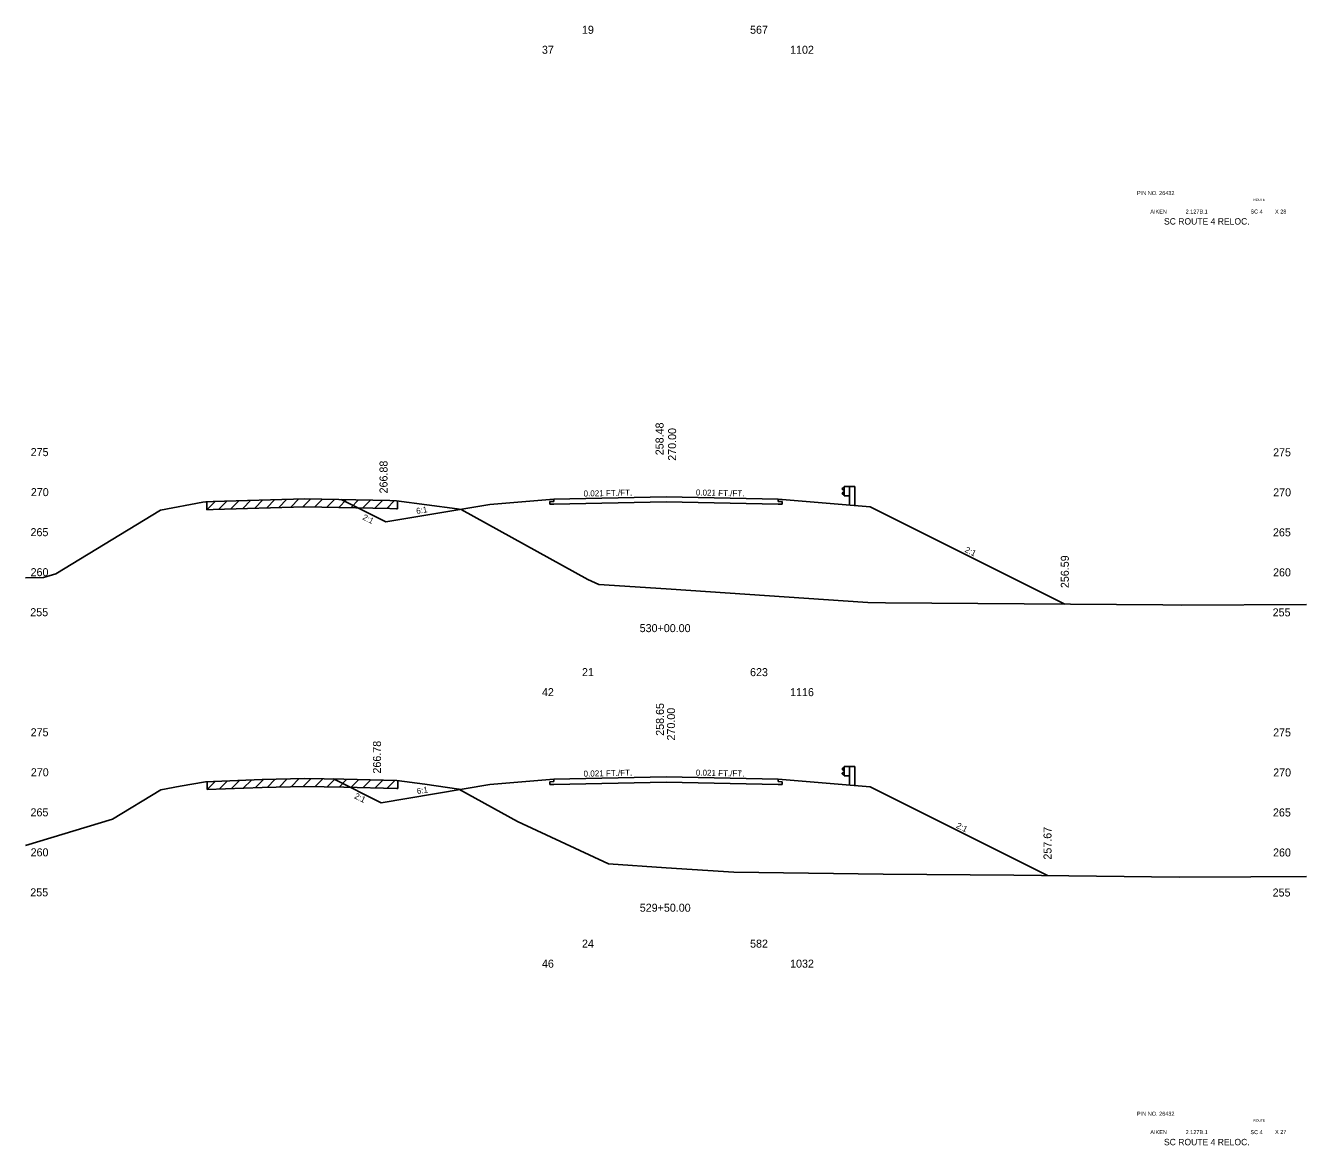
# Model space of a CAD drawing. Extents: x 2967 to 4323, y -3677 to -817.
# Drawn here: x 3555.3 to 3715.3, y -3465.9 to -3326 of the extents above; entities that cross this region are included whole.
import ezdxf

# ---------------------------------------------------------------- set-up
doc = ezdxf.new("R2010")
doc.units = 0
for name, color, linetype in [('Level 1', 7, 'Continuous'), ('Level 10', 7, 'Continuous'), ('Level 11', 7, 'Continuous'), ('Level 12', 7, 'Continuous'), ('Level 20', 7, 'Continuous'), ('Level 24', 7, 'Continuous'), ('Level 3', 7, 'Continuous'), ('Level 32', 7, 'Continuous'), ('Level 33', 7, 'Continuous'), ('Level 59', 7, 'Continuous'), ('Level 6', 7, 'Continuous'), ('Level 60', 7, 'Continuous'), ('Level 61', 7, 'Continuous'), ('Level 7', 7, 'Continuous')]:
    doc.layers.add(name, color=color, linetype=linetype)

msp = doc.modelspace()

# ---------------------------------------------------------------- linework, layer by layer
at = {"layer": 'Level 11'}
for p, q in [((3621.35, -3385.43), (3620.85, -3385.44)), ((3620.85, -3385.44), (3620.85, -3385.78)), ((3621.35, -3385.13), (3621.35, -3385.43)), ((3649.35, -3385.43), (3649.35, -3385.13)), ((3649.85, -3385.44), (3649.35, -3385.43)), ((3649.85, -3385.78), (3649.85, -3385.44)), ((3620.85, -3385.78), (3621.35, -3385.77)), ((3649.35, -3385.77), (3649.85, -3385.78)), ((3621.35, -3420.43), (3620.85, -3420.44)), ((3620.85, -3420.44), (3620.85, -3420.78)), ((3620.85, -3420.78), (3621.35, -3420.77)), ((3621.35, -3420.13), (3621.35, -3420.43)), ((3649.35, -3420.43), (3649.35, -3420.13)), ((3649.85, -3420.44), (3649.35, -3420.43)), ((3649.35, -3420.77), (3649.85, -3420.78)), ((3649.85, -3420.78), (3649.85, -3420.44))]:
    msp.add_line(p, q, dxfattribs=at)
at = {"layer": 'Level 12'}
for p, q in [((3635.35, -3385.48), (3621.35, -3385.77)), ((3649.35, -3385.77), (3635.35, -3385.48)), ((3635.35, -3420.48), (3621.35, -3420.77)), ((3649.35, -3420.77), (3635.35, -3420.48))]:
    msp.add_line(p, q, dxfattribs=at)
at = {"layer": 'Level 24'}
for p, q in [((3657.62, -3383.62), (3657.35, -3383.82)), ((3657.35, -3383.82), (3657.35, -3383.87)), ((3657.35, -3383.87), (3657.62, -3384.07)), ((3657.62, -3384.72), (3657.62, -3383.55)), ((3657.62, -3383.55), (3658.28, -3383.55)), ((3658.28, -3383.55), (3658.28, -3385.88)), ((3658.28, -3383.55), (3658.95, -3383.55)), ((3658.95, -3383.55), (3658.95, -3385.93)), ((3657.35, -3384.39), (3657.62, -3384.19)), ((3657.35, -3384.44), (3657.35, -3384.39)), ((3657.62, -3384.64), (3657.35, -3384.44)), ((3657.62, -3384.72), (3658.29, -3384.72)), ((3657.62, -3418.62), (3657.35, -3418.82)), ((3657.35, -3418.82), (3657.35, -3418.87)), ((3657.35, -3418.87), (3657.62, -3419.07)), ((3657.35, -3419.39), (3657.62, -3419.19)), ((3657.62, -3419.72), (3657.62, -3418.55)), ((3657.62, -3418.55), (3658.28, -3418.55)), ((3658.28, -3418.55), (3658.28, -3420.88)), ((3658.28, -3418.55), (3658.95, -3418.55)), ((3658.95, -3418.55), (3658.95, -3420.93)), ((3657.35, -3419.44), (3657.35, -3419.39)), ((3657.62, -3419.64), (3657.35, -3419.44)), ((3657.62, -3419.72), (3658.29, -3419.72))]:
    msp.add_line(p, q, dxfattribs=at)
at = {"layer": 'Level 59'}
for p, q in [((3621.35, -3385.13), (3635.35, -3384.84)), ((3635.35, -3384.84), (3649.35, -3385.13)), ((3621.35, -3420.13), (3635.35, -3419.84)), ((3635.35, -3419.84), (3649.35, -3420.13))]:
    msp.add_line(p, q, dxfattribs=at)
at = {"layer": 'Level 6'}
for p, q in [((3613.35, -3385.8), (3621.35, -3385.13)), ((3649.35, -3385.13), (3657.35, -3385.8)), ((3657.35, -3385.8), (3660.85, -3386.09)), ((3613.35, -3420.8), (3621.35, -3420.13)), ((3649.35, -3420.13), (3657.35, -3420.8)), ((3657.35, -3420.8), (3660.85, -3421.09))]:
    msp.add_line(p, q, dxfattribs=at)
at = {"layer": 'Level 60'}
for p, q in [((3572.21, -3386.52), (3577.47, -3385.53)), ((3577.47, -3385.53), (3577.87, -3385.46)), ((3577.87, -3385.46), (3578.77, -3385.43)), ((3578.77, -3385.43), (3590.24, -3385.08)), ((3590.24, -3385.08), (3600.84, -3385.31)), ((3600.84, -3385.31), (3601.66, -3385.33)), ((3601.66, -3385.33), (3609.24, -3386.33)), ((3559.12, -3394.48), (3572.21, -3386.52)), ((3609.24, -3386.33), (3609.76, -3386.41)), ((3609.76, -3386.41), (3625.6, -3395.16)), ((3555.35, -3394.95), (3557.57, -3394.94)), ((3557.57, -3394.94), (3559.12, -3394.48)), ((3625.6, -3395.16), (3626.97, -3395.8)), ((3626.97, -3395.8), (3635.35, -3396.36)), ((3635.35, -3396.36), (3660.58, -3398.04)), ((3660.58, -3398.04), (3662.76, -3398.07)), ((3662.76, -3398.07), (3697.42, -3398.35)), ((3697.42, -3398.35), (3699.76, -3398.38)), ((3699.76, -3398.38), (3715.35, -3398.31)), ((3574.66, -3420.99), (3577.82, -3420.44)), ((3577.82, -3420.44), (3584.91, -3420.18)), ((3584.91, -3420.18), (3590.2, -3420.02)), ((3590.2, -3420.02), (3595.09, -3420.12)), ((3595.09, -3420.12), (3601.72, -3420.29)), ((3601.72, -3420.29), (3605.22, -3420.75)), ((3605.22, -3420.75), (3609.48, -3421.37)), ((3566.19, -3425.12), (3572.23, -3421.45)), ((3572.23, -3421.45), (3574.66, -3420.99)), ((3609.48, -3421.37), (3616.8, -3425.42)), ((3555.35, -3428.39), (3566.19, -3425.12)), ((3616.8, -3425.42), (3628.18, -3430.71)), ((3628.18, -3430.71), (3635.35, -3431.19)), ((3635.35, -3431.19), (3643.83, -3431.75)), ((3643.83, -3431.75), (3662.47, -3431.99)), ((3662.47, -3431.99), (3678.79, -3432.13)), ((3678.79, -3432.13), (3699.47, -3432.36)), ((3699.47, -3432.36), (3708.41, -3432.32)), ((3708.41, -3432.32), (3715.35, -3432.29))]:
    msp.add_line(p, q, dxfattribs=at)
at = {"layer": 'Level 61'}
for p, q in [((3579.01, -3385.42), (3577.97, -3386.46)), ((3577.97, -3385.46), (3577.97, -3386.46)), ((3580.5, -3385.37), (3579.47, -3386.4)), ((3582, -3385.33), (3580.97, -3386.36)), ((3583.5, -3385.28), (3582.47, -3386.31)), ((3585, -3385.24), (3583.97, -3386.27)), ((3586.5, -3385.19), (3585.47, -3386.23)), ((3588, -3385.15), (3586.97, -3386.18)), ((3589.5, -3385.1), (3588.47, -3386.14)), ((3590.96, -3385.1), (3589.97, -3386.09)), ((3592.45, -3385.13), (3591.47, -3386.11)), ((3593.95, -3385.16), (3592.97, -3386.14)), ((3595.45, -3385.19), (3594.47, -3386.17)), ((3596.95, -3385.22), (3595.97, -3386.2)), ((3598.45, -3385.26), (3597.47, -3386.23)), ((3599.95, -3385.29), (3598.97, -3386.27)), ((3601.45, -3385.32), (3600.47, -3386.3)), ((3601.82, -3386.35), (3601.82, -3385.35)), ((3577.97, -3386.46), (3578.77, -3386.43)), ((3578.77, -3386.43), (3590.24, -3386.08)), ((3590.24, -3386.08), (3600.84, -3386.31)), ((3600.84, -3386.31), (3601.66, -3386.33)), ((3601.66, -3386.33), (3601.82, -3386.35)), ((3579.05, -3420.39), (3578.01, -3421.43)), ((3578.01, -3420.43), (3578.01, -3421.43)), ((3580.55, -3420.34), (3579.51, -3421.38)), ((3582.05, -3420.28), (3581.01, -3421.32)), ((3583.55, -3420.23), (3582.51, -3421.26)), ((3585.05, -3420.17), (3584.01, -3421.21)), ((3586.54, -3420.13), (3585.51, -3421.16)), ((3588.04, -3420.08), (3587.01, -3421.11)), ((3589.54, -3420.04), (3588.51, -3421.07)), ((3591, -3420.03), (3590.01, -3421.02)), ((3592.49, -3420.07), (3591.51, -3421.04)), ((3593.99, -3420.1), (3593.01, -3421.08)), ((3595.49, -3420.13), (3594.51, -3421.11)), ((3596.99, -3420.17), (3596.01, -3421.14)), ((3598.49, -3420.21), (3597.51, -3421.18)), ((3599.99, -3420.24), (3599.01, -3421.22)), ((3601.49, -3420.28), (3600.51, -3421.26)), ((3601.86, -3421.3), (3601.86, -3420.3)), ((3578.01, -3421.43), (3584.91, -3421.18)), ((3584.91, -3421.18), (3590.2, -3421.02)), ((3590.2, -3421.02), (3595.09, -3421.12)), ((3595.09, -3421.12), (3601.72, -3421.29)), ((3601.72, -3421.29), (3601.86, -3421.3))]:
    msp.add_line(p, q, dxfattribs=at)
at = {"layer": 'Level 7'}
for p, q in [((3594.77, -3385.18), (3600.35, -3387.97)), ((3600.35, -3387.97), (3613.35, -3385.8)), ((3660.85, -3386.09), (3685.17, -3398.25)), ((3593.8, -3420.09), (3599.75, -3423.07)), ((3599.75, -3423.07), (3613.35, -3420.8)), ((3660.85, -3421.09), (3683.01, -3432.17))]:
    msp.add_line(p, q, dxfattribs=at)

# ---------------------------------------------------------------- texts
at = {"layer": 'Level 1'}
for s, p in [('19', (3624.85, -3326.99)), ('567', (3645.85, -3326.99)), ('37', (3619.85, -3329.49)), ('1102', (3650.85, -3329.49)), ('21', (3624.85, -3407.25)), ('623', (3645.85, -3407.25)), ('42', (3619.85, -3409.75)), ('1116', (3650.85, -3409.75)), ('24', (3624.85, -3441.17)), ('582', (3645.85, -3441.17)), ('46', (3619.85, -3443.67)), ('1032', (3650.85, -3443.67))]:
    msp.add_text(s, height=1, dxfattribs=at).set_placement(p)
at = {"layer": 'Level 10'}
for s, p in [('258.48', (3635.04, -3379.65)), ('258.65', (3635.09, -3414.7))]:
    msp.add_text(s, height=1, rotation=90, dxfattribs=at).set_placement(p)
for s, p in [('530+00.00', (3632.06, -3401.75)), ('529+50.00', (3632.07, -3436.68))]:
    msp.add_text(s, height=1, dxfattribs=at).set_placement(p)
at = {"layer": 'Level 20'}
for s, height, p in [('PIN NO. 26432', 0.5, (3694.19, -3347.14)), ('ROUTE', 0.3, (3708.73, -3347.88)), ('AIKEN', 0.5, (3695.85, -3349.45)), ('SC ROUTE 4 RELOC.', 0.8, (3697.56, -3350.83)), (' 2.127B.1', 0.5, (3700.07, -3349.45)), ('SC 4', 0.5, (3708.36, -3349.45)), ('X 28', 0.5, (3711.43, -3349.45)), ('PIN NO. 26432', 0.5, (3694.19, -3462.17)), ('AIKEN', 0.5, (3695.85, -3464.47)), (' 2.127B.1', 0.5, (3700.07, -3464.47)), ('SC 4', 0.5, (3708.36, -3464.47)), ('ROUTE', 0.3, (3708.73, -3462.91)), ('X 27', 0.5, (3711.43, -3464.44)), ('SC ROUTE 4 RELOC.', 0.8, (3697.56, -3465.86))]:
    msp.add_text(s, height=height, dxfattribs=at).set_placement(p)
at = {"layer": 'Level 3'}
for s, p in [(' 275', (3555.61, -3379.76)), (' 275', (3710.82, -3379.78)), (' 270', (3555.63, -3384.76)), (' 270', (3710.83, -3384.78)), (' 265', (3555.59, -3389.76)), (' 265', (3710.8, -3389.78)), (' 260', (3555.6, -3394.76)), (' 260', (3710.81, -3394.78)), (' 255', (3555.56, -3399.76)), (' 255', (3710.76, -3399.78)), (' 275', (3555.61, -3414.76)), (' 275', (3710.82, -3414.78)), (' 270', (3555.63, -3419.76)), (' 270', (3710.83, -3419.78)), (' 265', (3555.59, -3424.76)), (' 265', (3710.8, -3424.78)), (' 260', (3555.6, -3429.76)), (' 260', (3710.81, -3429.78)), (' 255', (3555.56, -3434.76)), (' 255', (3710.76, -3434.78))]:
    msp.add_text(s, height=1, dxfattribs=at).set_placement(p)
at = {"layer": 'Level 32'}
for s, rotation, p in [('0.021 FT./FT.', 1.1916, (3625.06, -3384.81)), ('0.021 FT./FT.', 358.8084, (3639.07, -3384.67)), ('2:1', 333.435, (3597.36, -3387.64)), ('6:1', 9.4623, (3604.2, -3387)), ('2:1', 333.435, (3672.61, -3391.7)), ('0.021 FT./FT.', 1.1916, (3625.06, -3419.81)), ('0.021 FT./FT.', 358.8084, (3639.07, -3419.67)), ('2:1', 333.435, (3596.34, -3422.47)), ('6:1', 9.4623, (3604.28, -3422)), ('2:1', 333.435, (3671.53, -3426.16))]:
    msp.add_text(s, height=0.75, rotation=rotation, dxfattribs=at).set_placement(p)
at = {"layer": 'Level 33'}
for s, p in [('266.88', (3600.56, -3384.42)), ('256.59', (3685.67, -3396.25)), ('266.78', (3599.74, -3419.42)), ('257.67', (3683.51, -3430.17))]:
    msp.add_text(s, height=1, rotation=90, dxfattribs=at).set_placement(p)
at = {"layer": 'Level 59'}
for p in [(3636.61, -3380.71), (3636.48, -3415.66)]:
    msp.add_text(' 270.00', height=1, rotation=90, dxfattribs=at).set_placement(p)

doc.saveas('drawing.dxf')
